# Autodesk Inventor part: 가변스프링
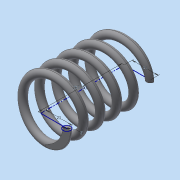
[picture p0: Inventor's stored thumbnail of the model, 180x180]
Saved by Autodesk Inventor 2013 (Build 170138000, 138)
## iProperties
Created: 2019-10
Part Number: 가변스프링
Material: 일반
Document SubType Name: Modeling
Designer: Administrator
Density: 1 g/cm^3
Author: Administrator
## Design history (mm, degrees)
sketch "스케치1"
  geometry: L1 (0, 0)-(0, 67.25); L2 (0, 0)-(21, 0); L3 (0, 67.25)-(21, 67.25); C1 r 3 at (21, 0)
  constraints: 6 end point, 1 centre point, 1 coincident, 1 parallel, 1 perpendicular, 1 vertical
  dimensions: "d0" = 67.25 distance of L1.start L1.end (derived); "d1" = 21 distance of L1.start L2.end; "d2" = 6 diameter of C1; "d3" = 21 distance of L1.end L3.end
feature "코일1" sketch "스케치1" pitch "d4" = 10; turns "d6" = 5; dims "d5" = 67.25 (= d0), "d7" = 0, angle "d8" = 90 deg, angle "d9" = 90 deg, "d10" = 0, "d11" = 0
sketch "스케치2"
  geometry: L1 (67.25, 30)-(0, 30); L2 (0, 30)-(0, -30); L3 (0, -30)-(67.25, -30); L4 (67.25, -30)-(67.25, 30); 1 further point
  constraints: 8 end point, 2 midpoint, 2 parallel, 1 horizontal, 1 perpendicular
  dimensions: "d12" = 60 distance between parallel lines of L3 L1; "d15" = 67.25 distance of L1.start L1.end (= d0)
extrude "돌출1" sketch "스케치2" stored distance "d16" = 0; taper "d17" = 0 deg
node "솔리드1"
